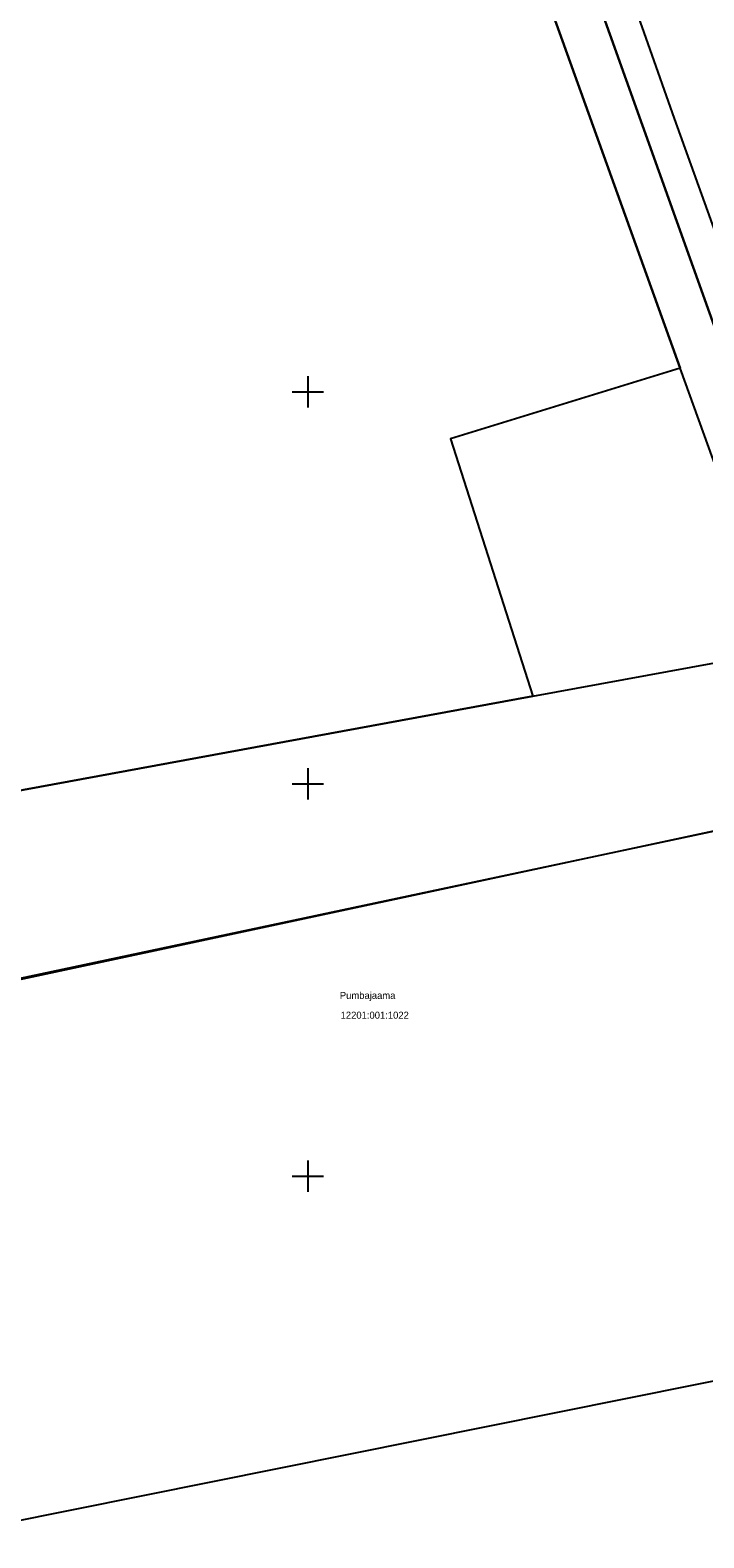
# Model space of a CAD drawing. Extents: x 692620 to 696053, y 6545308 to 6546689.
# Drawn here: x 695764.6 to 695850.5, y 6545803.9 to 6545996.1 of the extents above; entities that cross this region are included whole.
import ezdxf

# ---------------------------------------------------------------- set-up
doc = ezdxf.new("R2010")
doc.units = 0
for name, color, linetype in [('L_AADRESS', 7, 'Continuous'), ('PIIR', 7, 'Continuous'), ('TUNNUS', 7, 'Continuous'), ('VORK', 7, 'Continuous')]:
    doc.layers.add(name, color=color, linetype=linetype)

# ---------------------------------------------------------------- blocks, each defined once
blk = doc.blocks.new('VKORIS')
for p, q in [((0, 4), (0, -4)), ((-4, 0), (4, 0))]:
    blk.add_line(p, q)

msp = doc.modelspace()

# ---------------------------------------------------------------- linework, layer by layer
at = {"layer": 'PIIR'}
for points in [[(695765.77, 6546198.92), (695789.32, 6546206.54), (695813.14, 6546214.08), (695836.85, 6546221.81), (695860.69, 6546229.33), (695863.85, 6546219.82), (695859.72, 6546218.48), (695836.29, 6546211.12), (695827, 6546208.12), (695805.31, 6546201.08), (695798.34, 6546198.94), (695773.02, 6546190.73), (695786.41, 6546153.06), (695799.99, 6546115.28), (695813.41, 6546077.62), (695827.19, 6546040.09), (695843.34, 6545994.34), (695846.72, 6545984.85), (695870.54, 6545918.67), (695866.22, 6545918.1), (695765.77, 6546198.92)], [(695760.28, 6546197.13), (695765.77, 6546198.92), (695866.22, 6545918.1), (695860.5, 6545917.02), (695847.47, 6545952.98), (695823.7, 6546019.14), (695820.85, 6546027.55), (695804.99, 6546071.93), (695794.64, 6546100.17), (695791.42, 6546109.54), (695777.39, 6546148.63), (695763.47, 6546187.36), (695760.28, 6546197.13)], [(695704.17, 6545998.28), (695724.86, 6546004.52), (695744.73, 6546004.37), (695770.04, 6546019.86), (695791.54, 6546023.93), (695823.7, 6546019.14), (695847.47, 6545952.98), (695818.2, 6545943.97), (695828.67, 6545911.2), (695737.81, 6545894.5), (695704.17, 6545998.28)], [(695479.61, 6545845.6), (695492.02, 6545844.12), (695522.36, 6545845.82), (695556.86, 6545854.09), (695582.19, 6545860.15), (695613.3, 6545867.49), (695676.5, 6545881.21), (695737.81, 6545894.5), (695828.67, 6545911.2), (695860.5, 6545917.02)], [(695853.53, 6545894.34), (695704.81, 6545862.54), (695663.31, 6545855.22), (695618.7, 6545847.36), (695586.95, 6545839.52), (695564.09, 6545833.71), (695526.65, 6545824.18), (695492.76, 6545821.44), (695341.1, 6545839.24)], [(695749.06, 6545872.21), (695853.53, 6545894.34), (695858.28, 6545825.17), (695752.23, 6545803.88), (695749.06, 6545872.21)]]:
    msp.add_lwpolyline(points, dxfattribs=at)

# ---------------------------------------------------------------- block references
at = {"layer": 'VORK', "xscale": 0.5, "yscale": 0.5}
for p in [(695800, 6545950), (695800, 6545900), (695800, 6545850)]:
    msp.add_blockref('VKORIS', p, dxfattribs=at)

# ---------------------------------------------------------------- texts
at = {"layer": 'L_AADRESS'}
msp.add_text('Pumbajaama', height=0.9, dxfattribs=at).set_placement((695804.07, 6545872.58))
at = {"layer": 'TUNNUS'}
msp.add_text('12201:001:1022', height=0.9, dxfattribs=at).set_placement((695804.17, 6545870.06))

doc.saveas('drawing.dxf')
